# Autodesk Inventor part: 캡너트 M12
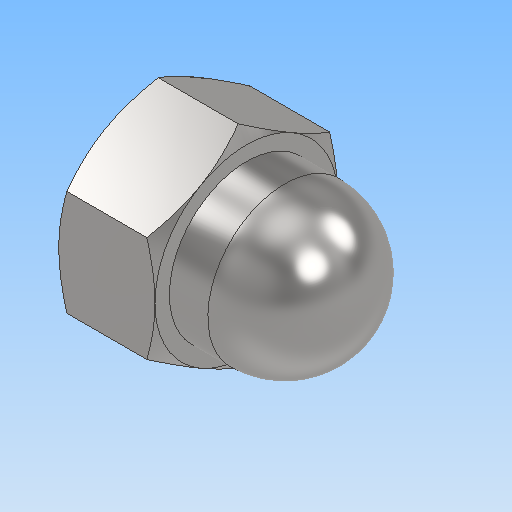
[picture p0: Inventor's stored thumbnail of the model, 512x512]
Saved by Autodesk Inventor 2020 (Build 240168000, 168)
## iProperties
Created: 2024-07
Part Number: 캡너트 M12
Material: 강철, 연강
Description: 6각 둥근캡 너트
Document SubType Name: Modeling
Designer: oem
Density: 7.85 g/cm^3
Appearance: 기본값
Author: jhkim
Sending System: Autodesk Inventor 2025
Preprocessor: ST-DEVELOPER v20
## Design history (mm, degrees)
feature "Solid1"
node "솔리드1"
